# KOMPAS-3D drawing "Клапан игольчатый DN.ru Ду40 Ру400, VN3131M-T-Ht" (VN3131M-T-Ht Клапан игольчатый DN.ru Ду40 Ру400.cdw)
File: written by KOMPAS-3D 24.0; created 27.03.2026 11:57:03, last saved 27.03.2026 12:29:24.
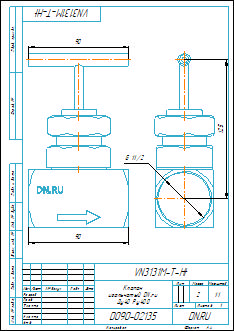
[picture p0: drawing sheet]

Document properties: Автор: Илья; Форматы листов документа: A4; Полное имя файла: VN3131M-T-Ht Клапан игольчатый DN.ru Ду40 Ру400.m3d; Масса: 2; Наименование: Клапан игольчатый DN.ru Ду40 Ру400; Количество листов документа: 1; Примечание: D090-02135

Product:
- Body: Body4  | qty 1
    Масса: 2.135076
- Part/product: Клапан игольчатый DN.ru Ду40 Ру400  | designation VN3131M-T-Ht
    Масса: 2
    Раздел спецификации: Прочие изделия
    Примечание: D090-02135

Views: Вид 1, Слева, Проекционный вид 2
Referenced files in D:\Обмен\Заказы с фриланса\DN.ru\VNxxM-T-Ht Клапан игольчатый DN.ru Ду8-50 Ру400\VN3232M-T-Ht Клапан игольчатый DN.ru Ду8-50 Ру400\DN8\: VN3232M-T-Ht Клапан игольчатый DN.ru Ду8 Ру400.m3d, VN3232M-T-Ht Клапан игольчатый DN.ru Ду8 Ру400.cdw
Referenced files in D:\Обмен\Заказы с фриланса\DN.ru\VNxxM-T-Ht Клапан игольчатый DN.ru Ду8-50 Ру400\VN3131M-T-Ht Клапан игольчатый DN.ru Ду8-50 Ру400\DN40\: VN3131M-T-Ht Клапан игольчатый DN.ru Ду40 Ру400.m3d
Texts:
  VN3131M-T-Ht
  Клапан
  игольчатый DN.ru
  Ду40 Ру400
  Body4
  Клапан игольчатый DN.ru Ду40 Ру400
  VN3131M-T-Ht Клапан игольчатый DN.ru Ду40 Ру400
Dimensions and other numbers on the sheet: 0; 3; 2; 4; 90; 125; 1:1; 1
